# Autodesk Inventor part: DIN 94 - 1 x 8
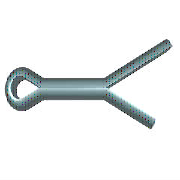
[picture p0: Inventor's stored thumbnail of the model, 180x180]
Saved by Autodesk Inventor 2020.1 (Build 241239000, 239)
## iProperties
Created: 2019-01
Part Number: DIN 94 - 1 x 8
Material: Steel, Mild
Description: Split Pin
Document SubType Name: Modeling
Standard: DIN 94
Designer: Safarabadi
Standards Organization: DIN
Language: en-US
Size Designation: 1 x 8
Categories: <MemberInstance><Categories><Category DisplayName="Fasteners" InternalName="e4da775c-781d-43d5-af7c-5136215cf5a6" Mnemonic="FSTN"><Category DisplayName="Pins" I
Density: 7.85 g/cm^3
Appearance: Semi-Polished
IsCustomPart: 1
Author: Safarabadi
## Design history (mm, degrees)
sketch "Sketch1"
  geometry: L1 (0, 0.45)-(4, 0.45); L2 (0, -0.45)-(4, -0.45); L3 (4, 0.45)-(8, 1.982); L4 (8, 1.982)-(8.15, 1.59); L5 (8.15, 1.59)-(4, 0); L6 (4, 0)-(9.75, -2.203); L7 (9.75, -2.203)-(9.6, -2.595); L8 (9.6, -2.595)-(4, -0.45); L9 (0, 0)-(-2.004, -0.44); L10 (0, 0)-(-2.004, 0.44); L11 (0, 0.45)-(0, -0.45); L12 (0, 0.45)-(-1.902, 0.878); L13 (0, -0.45)-(-1.902, -0.878); L14 (-3, 0)-(4, 0); L15 (4, 0.45)-(4, -0.45); A1 r 0.9 centre (-2.1, 0) between (-1.902, 0.878) and (-1.902, -0.878); A2 r 0.45 centre (-2.1, 0) between (-2.004, 0.44) and (-2.004, -0.44); 1 further point
  constraints: 30 end point, 5 point on circle, 4 parallel, 4 perpendicular, 4 point on line, 4 tangent, 2 centre point, 2 midpoint, 1 coincident, 1 horizontal
  dimensions: "d0" = 4 distance of L1.start L1.end (= MSIAB); "d1" = 8 horizontal distance of L1.start L3.end (= SNLG); "d2" = 159.037 deg angle of L1 L3; "d3" = 159.037 deg angle of L2 L8; "d4" = 1.6 horizontal distance of L3.end L7.end (= LGDIF); "d5" = 0.45 radius of A2 (= -0.5 x SNND1 + 0.5 x KBR); "d6" = 0.9 radius of A1 (= 0.5 x KBR); "d7" = 0.45 distance from line of L1 L9.start (= 0.5 x SNND1); "d8" = 0.45 distance between parallel lines of L2 L14 (= 0.5 x SNND1); "d9" = 2.1 distance from line of L11 A1.centre (= KOL - 0.5 x KBR)
extrude "Body" new body sketch "Sketch1" stored distance "d10" = 0.9 (= SNND1); taper "d11" = 0 deg
workaxis "Work Axis1"
workplane "Work Plane1"
body "Solid1"
fillet "Fillet" dims "d12" = 0.315 (= 0.35 x SNND1)
workplane "Work Plane3"
other parameters: "SNND" = 1 [user parameter; used in 1 equation term], "SNLG" = 8 [user parameter; used in 1 equation term], "SNND1" = 0.9 [user parameter; used in 5 equation terms], "KBR" = 1.8 [user parameter; used in 3 equation terms], "KOL" = 3 [user parameter; used in 1 equation term], "LGDIF" = 1.6 [user parameter; used in 1 equation term], "MSIAB" = 4 [user parameter; used in 1 equation term], "d15" = 0, "d16" = 0, "d17" = 0, "BDMI" = 3 [user parameter], "NNDMIN" = 3.5 [user parameter], "SPBOR" = 1 (= SNND) [user parameter], "DSH" = 2.2 [user parameter], "NNDMAX" = 4.5 [user parameter], "PNDST" = 4 [user parameter], "BDMA" = 4 [user parameter]
